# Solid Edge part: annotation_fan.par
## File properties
Author: alogan
Template: Sync Iso Part.par
Last saved by: rkriggs
Revision: 34
Application: Solid Edge
Accuracy: 0.990
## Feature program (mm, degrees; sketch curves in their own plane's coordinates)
pattern "PatternOccurrence_1"  XCount = 4; XOffset = 90 deg
pattern "PatternOccurrence_16"  XCount = 8; XOffset = 45 deg
hole "unnamed Hole 1" through
hole "unnamed Hole 2" through
hole "unnamed Hole 3" through
pattern "PatternOccurrence_17"  XCount = 4; XOffset = 90 deg
sketch for "Hole_1" plane through (0, 0, 0) normal (1, 0, 0) x-axis (0, 1, 0)
hole "Hole_1" diameter 12 through
pattern "unnamed Pattern 2" of "Hole_1"
pattern "unnamed Pattern 1" of "Hole_1"
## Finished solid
Body 1: solid body, 77 faces, 192 edges, 112 vertices.
  Faces by surface: plane 49, cylinder 28
  Edges by curve: line 104, circle 88
Bounding box of the edges (mm): 34.988 x 131.066 x 131.066, from (-10, -65.533, -65.533) to (24.9878, 65.533, 65.533).
Cylindrical faces by radius (mm): R4.5 x1, R6 x4, R7 x4, R9.5 x1, R10 x8, R12.5 x4, R45 x1, R50 x1, R62.5 x4
Planar faces by outward normal: +x 15, +y 2, +z 2, -x 10, -y 2, -z 2, oblique 16
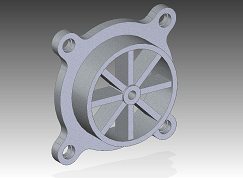
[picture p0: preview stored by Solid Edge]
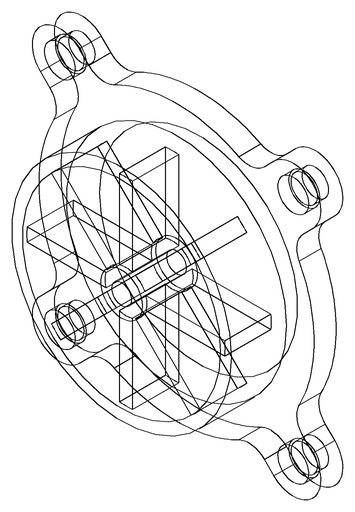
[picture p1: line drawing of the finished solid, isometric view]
